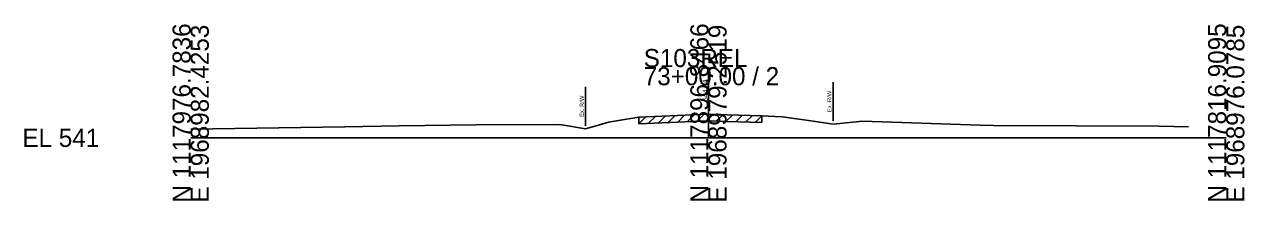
# Model space of a CAD drawing. Extents: x -26 to 163, y -10 to 24518.
# Drawn here: x -25.7 to 162.8, y 21490.3 to 21517.5 of the extents above; entities that cross this region are included whole.
import ezdxf

# ---------------------------------------------------------------- set-up
doc = ezdxf.new("R2010")
doc.units = 0
for name, color, linetype in [('RD_GPK_XS_Cell', 7, 'Continuous'), ('RD_XS_ExGround', 7, 'Continuous'), ('RD_XS_ExPaveRet', 7, 'Continuous'), ('RD_XS_ExRW', 7, 'Continuous'), ('RD_XS_TX_Elev_EX', 7, 'Continuous')]:
    doc.layers.add(name, color=color, linetype=linetype)

msp = doc.modelspace()

# ---------------------------------------------------------------- linework, layer by layer
at = {"layer": 'RD_GPK_XS_Cell'}
for p, q in [((80, 21500), (80, 21510.93)), ((0, 21500), (80, 21500)), ((80, 21500), (160, 21500))]:
    msp.add_line(p, q, dxfattribs=at)
at = {"layer": 'RD_XS_ExGround'}
msp.add_lwpolyline([(0, 21501.37), (23.84, 21501.68), (32.19, 21501.85), (44.07, 21502), (56.87, 21502.06), (57.32, 21501.99), (61.01, 21501.38), (63.14, 21502.03), (64.57, 21502.45), (66.11, 21502.69), (69.26, 21503.19), (76.42, 21503.49), (80.06, 21503.64), (82.83, 21503.55), (88.27, 21503.39), (90.33, 21503.32), (91.43, 21503.27), (96.53, 21502.53), (99.25, 21502.13), (102.29, 21502.44), (103.8, 21502.6), (121.99, 21501.98), (124.04, 21501.92), (149.6, 21501.8), (154.17, 21501.73)], dxfattribs=at)
at = {"layer": 'RD_XS_ExPaveRet'}
for p, q in [((69.26, 21502.19), (70.3, 21503.23)), ((69.26, 21502.19), (69.26, 21503.19)), ((69.26, 21502.19), (76.42, 21502.49)), ((70.76, 21502.25), (71.8, 21503.3)), ((72.26, 21502.32), (73.3, 21503.36)), ((73.76, 21502.38), (74.8, 21503.43)), ((75.26, 21502.45), (76.3, 21503.49)), ((76.42, 21502.49), (80.06, 21502.64)), ((76.76, 21502.51), (77.8, 21503.55)), ((78.26, 21502.57), (79.3, 21503.61)), ((79.76, 21502.63), (80.75, 21503.62)), ((80.06, 21502.64), (82.83, 21502.55)), ((81.26, 21502.61), (82.23, 21503.57)), ((82.76, 21502.56), (83.73, 21503.53)), ((82.83, 21502.55), (88.27, 21502.39)), ((84.26, 21502.51), (85.23, 21503.48)), ((85.76, 21502.46), (86.73, 21503.43)), ((87.26, 21502.42), (88.23, 21503.39)), ((88.27, 21503.39), (88.27, 21502.39))]:
    msp.add_line(p, q, dxfattribs=at)
at = {"layer": 'RD_XS_ExRW'}
for p, q in [((61.01, 21507.88), (61.01, 21501.88)), ((99.25, 21508.63), (99.25, 21502.63))]:
    msp.add_line(p, q, dxfattribs=at)

# ---------------------------------------------------------------- texts
at = {"layer": 'RD_GPK_XS_Cell'}
for s, p in [('N 1117976.7836', (0, 21490)), ('E 1968982.4253', (2.8, 21490)), ('N 1117896.8466', (80, 21490)), ('E 1968979.2519', (82.8, 21490)), ('N 1117816.9095', (160, 21490)), ('E 1968976.0785', (162.8, 21490))]:
    msp.add_text(s, height=2.8, rotation=90, dxfattribs=at).set_placement(p)
for s, p in [('S103REL', (70, 21510.93)), ('73+00.00 / 2', (70, 21508.13)), ('EL 541', (-26, 21498.6))]:
    msp.add_text(s, height=2.8, dxfattribs=at).set_placement(p)
at = {"layer": 'RD_XS_ExRW'}
for p in [(60.76, 21503.23), (99, 21503.98)]:
    msp.add_text('Ex. R/W ', height=0.65, rotation=90, dxfattribs=at).set_placement(p)
at = {"layer": 'RD_XS_TX_Elev_EX'}
msp.add_text('544.64', height=0.8, rotation=90, dxfattribs=at).set_placement((79.9, 21505.64))

doc.saveas('drawing.dxf')
